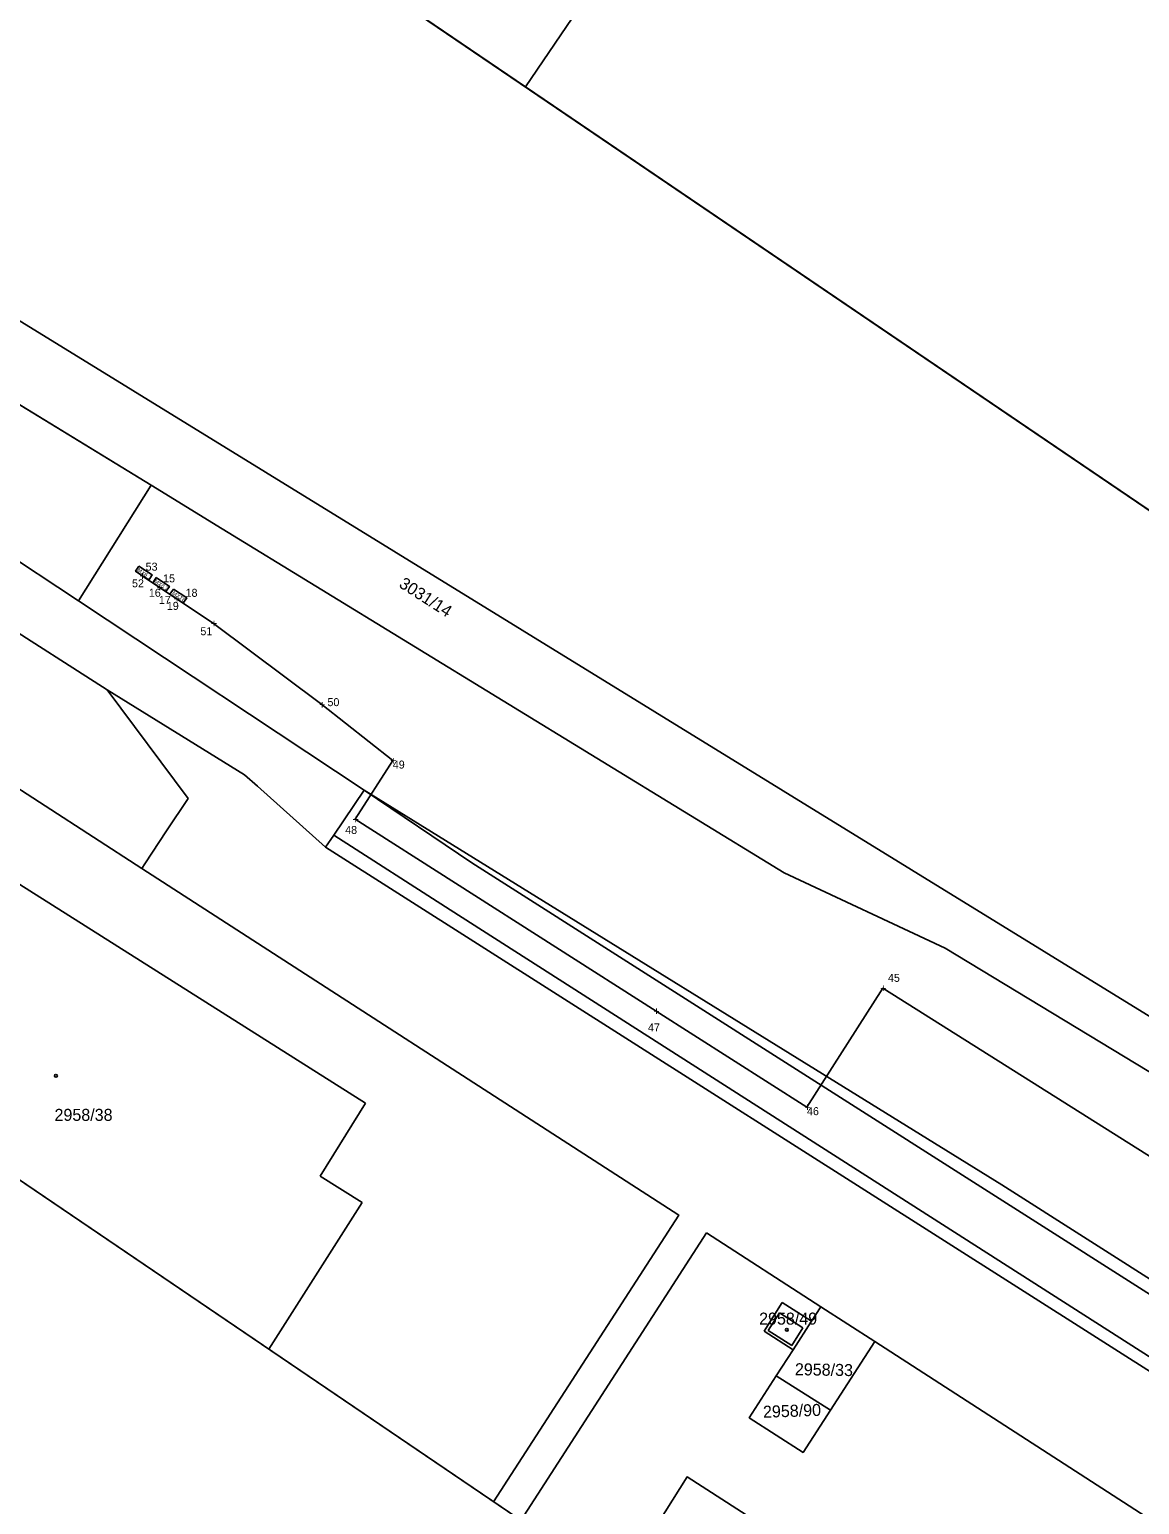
# Model space of a CAD drawing. Extents: x -621058 to -620110, y -1122807 to -1122030.
# Drawn here: x -620862.9 to -620724.3, y -1122448 to -1122263.7 of the extents above; entities that cross this region are included whole.
import ezdxf

# ---------------------------------------------------------------- set-up
doc = ezdxf.new("R2010")
doc.units = 0
for name, color, linetype in [('060601_EOV', 7, 'Continuous'), ('BODY', 7, 'Continuous'), ('BODY POPIS', 7, 'Continuous'), ('RÁMY', 7, 'Continuous'), ('Vrstva 53', 7, 'Continuous'), ('Vrstva 55', 7, 'Continuous'), ('Vrstva 56', 7, 'Continuous'), ('Vrstva 57', 7, 'Continuous')]:
    doc.layers.add(name, color=color, linetype=linetype)

msp = doc.modelspace()

# ---------------------------------------------------------------- linework, layer by layer
at = {"layer": '060601_EOV'}
msp.add_line((-620846.68, -1122333.42), (-620846.69, -1122333.43), dxfattribs=at)
for points in [[(-620849.23, -1122330.78), (-620847.57, -1122331.88), (-620848.01, -1122332.54), (-620849.66, -1122331.43)], [(-620847.07, -1122332.21), (-620845.42, -1122333.32), (-620845.86, -1122333.97), (-620847.51, -1122332.87)], [(-620844.92, -1122333.65), (-620843.27, -1122334.75), (-620843.7, -1122335.4), (-620845.36, -1122334.3)]]:
    msp.add_lwpolyline(points, close=True, dxfattribs=at)
for points in [[(-620538.89, -1122521.21), (-620599.21, -1122483.22), (-620683.52, -1122429.44), (-620756.33, -1122383.52), (-620765.8, -1122398.39), (-620784.65, -1122386.39), (-620822.22, -1122362.42), (-620817.53, -1122355.08), (-620826.41, -1122348.08), (-620839.92, -1122337.94), (-620848.84, -1122332), (-620848.83, -1122331.99)], [(-620844.53, -1122334.85), (-620844.53, -1122334.85), (-620844.54, -1122334.86)]]:
    msp.add_lwpolyline(points, dxfattribs=at)
at = {"layer": 'RÁMY'}
for points in [[(-620804.4, -1122089.05), (-620717.54, -1122148.04), (-620800.97, -1122270.89), (-620887.83, -1122211.9)], [(-620717.54, -1122148.04), (-620630.68, -1122207.04), (-620714.11, -1122329.88), (-620800.97, -1122270.89)], [(-620974.7, -1122152.91), (-620192.94, -1122683.83), (-620276.37, -1122806.68), (-621058.13, -1122275.76)], [(-620887.83, -1122211.9), (-620192.94, -1122683.83), (-620276.37, -1122806.68), (-620971.26, -1122334.75)]]:
    msp.add_lwpolyline(points, close=True, dxfattribs=at)
at = {"layer": 'Vrstva 53'}
for p, q in [((-620856.79, -1122335.14), (-620882.26, -1122318.28)), ((-620847.72, -1122320.67), (-620838.83, -1122326.12)), ((-620838.83, -1122326.12), (-620768.63, -1122369.09)), ((-620821.12, -1122358.76), (-620856.79, -1122335.14)), ((-620741.46, -1122408.09), (-620821.12, -1122358.76)), ((-620768.63, -1122369.09), (-620748.53, -1122378.52)), ((-620748.53, -1122378.52), (-620702.13, -1122406.7)), ((-620679.51, -1122447.56), (-620741.46, -1122408.09))]:
    msp.add_line(p, q, dxfattribs=at)
msp.add_lwpolyline([(-620907.48, -1122284.08), (-620847.72, -1122320.67), (-620856.79, -1122335.14)], dxfattribs=at)
at = {"layer": 'Vrstva 55'}
for p, q in [((-620907.48, -1122284.08), (-620847.72, -1122320.67)), ((-620866.03, -1122298.98), (-620688.16, -1122408.5)), ((-620848.87, -1122368.55), (-620933.94, -1122313.6)), ((-620894.54, -1122319.77), (-620853.22, -1122346.25)), ((-620856.79, -1122335.14), (-620882.26, -1122318.28)), ((-620856.79, -1122335.14), (-620847.72, -1122320.67)), ((-620847.72, -1122320.67), (-620838.83, -1122326.12)), ((-620838.83, -1122326.12), (-620768.63, -1122369.09)), ((-620821.12, -1122358.76), (-620856.79, -1122335.14)), ((-620836.04, -1122356.85), (-620853.22, -1122346.25)), ((-620853.22, -1122346.25), (-620843.09, -1122359.81)), ((-620834.44, -1122358.28), (-620836.04, -1122356.85)), ((-620825.92, -1122365.89), (-620834.44, -1122358.28)), ((-620843.09, -1122359.81), (-620845.8, -1122363.88)), ((-620824.91, -1122364.39), (-620821.12, -1122358.76)), ((-620821.12, -1122358.76), (-620741.46, -1122408.09)), ((-620807.67, -1122367.84), (-620821.12, -1122358.76)), ((-620845.8, -1122363.88), (-620848.5, -1122367.99)), ((-620872.17, -1122365.51), (-620820.94, -1122397.9)), ((-620824.91, -1122364.39), (-620825.92, -1122365.89)), ((-620684.91, -1122455.63), (-620825.92, -1122365.89)), ((-620645.72, -1122471.03), (-620807.67, -1122367.84)), ((-620848.5, -1122367.99), (-620848.87, -1122368.55)), ((-620768.63, -1122369.09), (-620748.53, -1122378.52)), ((-620748.53, -1122378.52), (-620702.13, -1122406.7)), ((-620826.62, -1122407), (-620820.94, -1122397.9)), ((-620821.36, -1122410.31), (-620826.62, -1122407)), ((-620741.46, -1122408.09), (-620679.51, -1122447.56)), ((-620833.01, -1122428.64), (-620821.36, -1122410.31)), ((-620778.34, -1122414.11), (-620801.54, -1122450.02)), ((-620764.06, -1122423.34), (-620778.34, -1122414.11)), ((-620768.9, -1122422.81), (-620771.15, -1122426.36)), ((-620768.9, -1122422.81), (-620765.22, -1122425.14)), ((-620764.06, -1122423.34), (-620765.22, -1122425.14)), ((-620757.34, -1122427.68), (-620764.06, -1122423.34)), ((-620771.15, -1122426.36), (-620767.52, -1122428.7)), ((-620765.22, -1122425.14), (-620767.52, -1122428.7)), ((-620767.52, -1122428.7), (-620769.63, -1122431.96)), ((-620762.87, -1122436.24), (-620757.34, -1122427.68)), ((-620702.74, -1122462.95), (-620757.34, -1122427.68)), ((-620762.87, -1122436.24), (-620769.63, -1122431.96))]:
    msp.add_line(p, q, dxfattribs=at)
for points in [[(-620804.95, -1122447.7), (-620781.81, -1122411.87), (-620848.87, -1122368.55)], [(-620769.63, -1122431.96), (-620773.01, -1122437.2), (-620766.29, -1122441.54), (-620762.87, -1122436.24)], [(-620758.93, -1122466.63), (-620763.57, -1122474.01), (-620789, -1122457.71), (-620780.78, -1122444.6), (-620755.36, -1122460.94)]]:
    msp.add_lwpolyline(points, dxfattribs=at)
at = {"layer": 'Vrstva 56'}
for p, q in [((-620824.91, -1122364.39), (-620810.36, -1122373.73)), ((-620810.36, -1122373.73), (-620648.08, -1122477.56)), ((-620770.64, -1122426.28), (-620769.25, -1122424.08)), ((-620769.25, -1122424.08), (-620766.31, -1122425.96)), ((-620770.64, -1122426.28), (-620767.68, -1122428.15)), ((-620767.68, -1122428.15), (-620766.31, -1122425.96))]:
    msp.add_line(p, q, dxfattribs=at)
at = {"layer": 'Vrstva 57'}
for centre in [(-620859.6, -1122394.47), (-620768.31, -1122426.2)]:
    msp.add_circle(centre, 0.175, dxfattribs=at)

# ---------------------------------------------------------------- texts
at = {"layer": '060601_EOV'}
for s, p in [('MX6.1', (-620849.52, -1122331.38)), ('MX6.2', (-620847.41, -1122332.79)), ('MXT6', (-620845.16, -1122334.29))]:
    msp.add_text(s, height=0.5, rotation=326.3315, dxfattribs=at).set_placement(p)
at = {"layer": 'BODY'}
for p in [(-620849.18, -1122332.5), (-620849.17, -1122332.49), (-620847.02, -1122333.93), (-620847.02, -1122333.92), (-620844.87, -1122335.36), (-620844.86, -1122335.35), (-620844.86, -1122335.35), (-620840.25, -1122338.44), (-620826.74, -1122348.58), (-620817.86, -1122355.58), (-620822.55, -1122362.92), (-620756.66, -1122384.02), (-620784.98, -1122386.89), (-620766.13, -1122398.89)]:
    msp.add_text('+', height=1, dxfattribs=at).set_placement(p)
at = {"layer": 'BODY POPIS'}
for s, p in [('53', (-620848.4, -1122331.35)), ('52', (-620850.1, -1122333.43)), ('15', (-620846.22, -1122332.81)), ('16', (-620848, -1122334.61)), ('17', (-620846.75, -1122335.51)), ('18', (-620843.41, -1122334.62)), ('19', (-620845.75, -1122336.25)), ('51', (-620841.56, -1122339.42)), ('50', (-620825.69, -1122348.28)), ('49', (-620817.53, -1122356.08)), ('48', (-620823.48, -1122364.25)), ('45', (-620755.69, -1122382.73)), ('47', (-620785.66, -1122388.93)), ('46', (-620765.8, -1122399.39))]:
    msp.add_text(s, height=1, dxfattribs=at).set_placement(p)
at = {"layer": 'Vrstva 57'}
for s, rotation, p in [('3031/14', 327.3665, (-620816.87, -1122333.33)), ('2958/33', 359.0608, (-620767.32, -1122431.88)), ('2958/90', 2.0095, (-620771.27, -1122437.21))]:
    msp.add_text(s, height=1.5, rotation=rotation, dxfattribs=at).set_placement(p)
for s, p in [('2958/38', (-620859.78, -1122400.1)), ('2958/49', (-620771.78, -1122425.56))]:
    msp.add_text(s, height=1.5, dxfattribs=at).set_placement(p)

doc.saveas('drawing.dxf')
